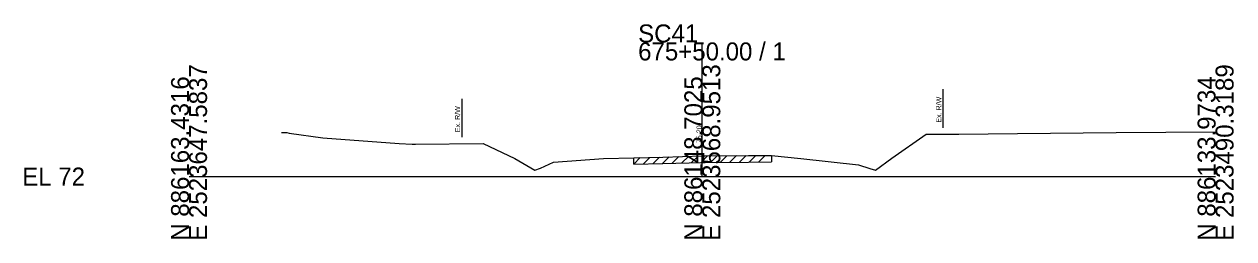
# Model space of a CAD drawing. Extents: x -26 to 183, y -10 to 24021.
# Drawn here: x -25.7 to 162.8, y 7990.3 to 8023.7 of the extents above; entities that cross this region are included whole.
import ezdxf

# ---------------------------------------------------------------- set-up
doc = ezdxf.new("R2010")
doc.units = 0
for name, color, linetype in [('RD_GPK_XS_Cell', 7, 'Continuous'), ('RD_XS_ExGround', 7, 'Continuous'), ('RD_XS_ExPaveRet', 7, 'Continuous'), ('RD_XS_ExRW', 7, 'Continuous'), ('RD_XS_TX_Elev_EX', 7, 'Continuous')]:
    doc.layers.add(name, color=color, linetype=linetype)

msp = doc.modelspace()

# ---------------------------------------------------------------- linework, layer by layer
at = {"layer": 'RD_GPK_XS_Cell'}
for p, q in [((80, 8000), (80, 8020.88)), ((0, 8000), (80, 8000)), ((80, 8000), (160, 8000))]:
    msp.add_line(p, q, dxfattribs=at)
at = {"layer": 'RD_XS_ExGround'}
for p, q in [((14.42, 8006.86), (15.26, 8006.88)), ((15.26, 8006.88), (15.6, 8006.75)), ((15.6, 8006.75), (20.84, 8006.04)), ((20.84, 8006.04), (32.73, 8005.17)), ((32.73, 8005.17), (34.78, 8005.05)), ((35.31, 8005.02), (45.82, 8005.17)), ((45.82, 8005.17), (50.78, 8002.83)), ((109.56, 8002.87), (114.89, 8006.58)), ((114.89, 8006.58), (119.98, 8006.6)), ((119.98, 8006.6), (129.11, 8006.71)), ((129.11, 8006.71), (144.5, 8006.85)), ((144.5, 8006.85), (160, 8006.96)), ((34.78, 8005.05), (35.31, 8005.02)), ((80, 8003.2), (80.47, 8003.21)), ((80.47, 8003.21), (87.19, 8003.26)), ((87.19, 8003.26), (90.78, 8003.29)), ((90.78, 8003.29), (95.33, 8002.79)), ((50.78, 8002.83), (53.9, 8001)), ((54.76, 8001.3), (56.83, 8002.26)), ((56.83, 8002.26), (64.59, 8002.79)), ((64.59, 8002.79), (69.31, 8002.93)), ((69.31, 8002.93), (73.85, 8003.04)), ((73.85, 8003.04), (80, 8003.2)), ((95.33, 8002.79), (104.33, 8001.84)), ((104.33, 8001.84), (106.1, 8001.27)), ((106.98, 8000.97), (109.56, 8002.87)), ((53.9, 8001), (54.76, 8001.3)), ((106.1, 8001.27), (106.98, 8000.97))]:
    msp.add_line(p, q, dxfattribs=at)
at = {"layer": 'RD_XS_ExPaveRet'}
for p, q in [((79.81, 8002.19), (80.83, 8003.21)), ((81.31, 8002.22), (82.32, 8003.22)), ((82.81, 8002.23), (83.82, 8003.23)), ((84.31, 8002.24), (85.32, 8003.25)), ((85.81, 8002.25), (86.82, 8003.26)), ((87.31, 8002.26), (88.32, 8003.27)), ((88.81, 8002.27), (89.82, 8003.28)), ((90.78, 8003.29), (90.78, 8002.29)), ((69.31, 8001.93), (70.33, 8002.95)), ((69.31, 8001.93), (69.31, 8002.93)), ((69.31, 8001.93), (73.85, 8002.04)), ((70.81, 8001.96), (71.83, 8002.99)), ((72.31, 8002), (73.33, 8003.03)), ((73.81, 8002.04), (74.83, 8003.07)), ((73.85, 8002.04), (80, 8002.2)), ((75.31, 8002.08), (76.33, 8003.1)), ((76.81, 8002.12), (77.83, 8003.14)), ((78.31, 8002.16), (79.33, 8003.18)), ((80, 8002.2), (80.47, 8002.21)), ((80.47, 8002.21), (87.19, 8002.26)), ((87.19, 8002.26), (90.78, 8002.29))]:
    msp.add_line(p, q, dxfattribs=at)
at = {"layer": 'RD_XS_ExRW'}
for p, q in [((117.5, 8013.59), (117.5, 8007.59)), ((42.5, 8012.12), (42.5, 8006.12))]:
    msp.add_line(p, q, dxfattribs=at)

# ---------------------------------------------------------------- texts
at = {"layer": 'RD_GPK_XS_Cell'}
for s, p in [('SC41', (70, 8020.88)), ('675+50.00 / 1', (70, 8018.08)), ('EL 72', (-26, 7998.6))]:
    msp.add_text(s, height=2.8, dxfattribs=at).set_placement(p)
for s, p in [('E 2523647.5837', (2.8, 7990)), ('E 2523568.9513', (82.8, 7990)), ('E 2523490.3189', (162.8, 7990)), ('N 886163.4316', (0, 7990)), ('N 886148.7025', (80, 7990)), ('N 886133.9734', (160, 7990))]:
    msp.add_text(s, height=2.8, rotation=90, dxfattribs=at).set_placement(p)
at = {"layer": 'RD_XS_ExRW'}
for p in [(42.25, 8006.91), (117.25, 8008.38)]:
    msp.add_text('Ex. R/W ', height=0.8, rotation=90, dxfattribs=at).set_placement(p)
at = {"layer": 'RD_XS_TX_Elev_EX'}
msp.add_text('75.20', height=0.8, rotation=90, dxfattribs=at).set_placement((79.9, 8005.2))

doc.saveas('drawing.dxf')
